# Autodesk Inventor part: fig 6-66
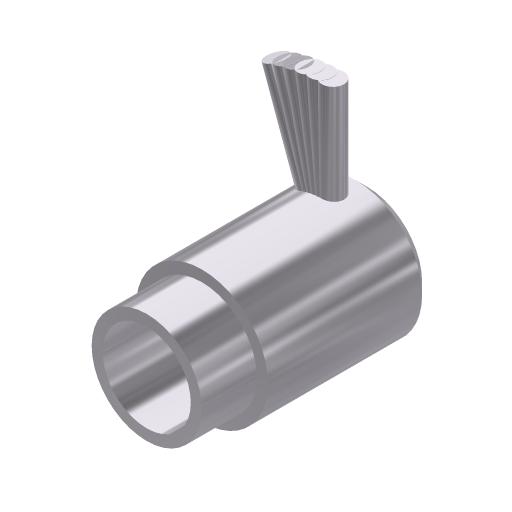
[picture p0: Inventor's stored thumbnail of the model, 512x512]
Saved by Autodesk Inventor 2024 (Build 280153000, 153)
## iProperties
Shininess: 77.0
Angle Display Precision: 2
Document Length Units: 11269
Document Angle Units: 11279
Document Time Units: 11290
Document Mass Units: 11283
Document Length Units Precision: 3
Document Angle Units Precision: 2
Compacted: True
Created: 2001-12
Part Number: fig 6-66
Document SubType Name: Modeling
Designer: Renu Muthoo
Density: 1 g/cm^3
Material: Generic
Appearance: Metal-AL-6061 (Polished)
Density: 0.0
Volumn: 0.0
Area: 0.0
PropertySet Name: Model Information
Control State: 0
Master: False
Checked Out: False
Author: Renu Muthoo
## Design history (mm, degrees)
sketch "Sketch2"
  geometry: L1 (-9.573, -4.327)-(-9.573, -5.327); L2 (-9.573, -5.327)-(-4.573, -5.327); L3 (-4.573, -5.327)-(-4.573, -6.327); L4 (-4.573, -6.327)-(9.427, -6.327); L5 (9.427, -6.327)-(10.427, -5.327); L6 (10.427, -5.327)-(10.427, -4.327); L7 (10.427, -4.327)-(-9.573, -4.327); L8 (-13.687, -0.327)-(14, -0.327)
  constraints: 16 end point, 5 parallel, 1 perpendicular, 1 vertical
  dimensions: "d9" = 20 distance of L6.end L1.start; "d10" = 5 distance of L1.end L2.end; "d11" = 12 diameter of L4 L8; "d12" = 10 diameter of L2 L8; "d13" = 8 diameter of L7 L8; "d14" = 45 deg angle of L5 L4; "d15" = 1 horizontal distance of L5.end L4.end
revolve "Revolution2" sketch "Sketch2" stored, may be unused: angle "d16" = 90 deg
workplane "Work Plane1"
workplane "Work Plane2"
sketch "Sketch3"
  geometry: L1 (-4, 8)-(4, 8) reference; C1 r 1 at (-0.098, 5)
  constraints: 1 centre point
  dimensions: "d18" = 3 distance from line of L1 C1.centre; "d19" = 2 diameter of C1
extrude "Extrusion1" join sketch "Sketch3" distance "d20" = 10; taper "d21" = 0 deg
pattern_circular "Circular Pattern3" dims angle "d29" = 20 deg
body "Solid1"
other parameters: "d17" = -1
